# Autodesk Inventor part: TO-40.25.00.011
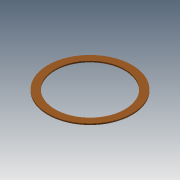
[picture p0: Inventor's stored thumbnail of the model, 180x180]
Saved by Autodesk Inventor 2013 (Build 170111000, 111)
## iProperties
Created: 2012-02
Part Number: TO-40.25.00.011
Material: Bronze, Soft Tin
Document SubType Name: Modeling
Designer: tedescj
Mass: 30.5184 g
Surface Area: 54.1734 cm^2
Volume: 3.43908 cm^3
Density: 8.874 g/cm^3
Author: tedescj
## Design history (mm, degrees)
sketch "Sketch1"
  geometry: C1 r 48.268 at (0, 0) reference; 1 further point
  constraints: 1 centre point, 2 other
extrude "Extrusion1" new body sketch "Sketch1" distance "d0" = 1.5; taper "d1" = 0 deg
sketch "Sketch2"
  geometry: C1 r 40 at (0, 0) reference; 1 further point
  constraints: 1 centre point, 2 other
extrude "Extrusion2" cut sketch "Sketch2" stored distance "d2" = 1.5; taper "d3" = 0 deg
body "Solid1"
